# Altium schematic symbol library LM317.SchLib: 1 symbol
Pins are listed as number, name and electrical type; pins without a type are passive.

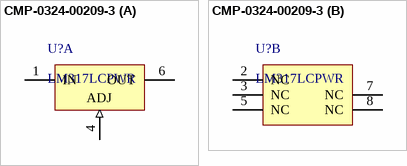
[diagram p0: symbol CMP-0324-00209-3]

## CMP-0324-00209-3
designator U?, comment LM317LCPWR
Adjustable Regulator with 3.7 to 38 V Input and 1.2 to 32 V Output, 0 to 125 degC, 8-Pin TSSOP (PW), Green (RoHS & no Sb/Br); Manufacturer: Texas Instruments; Iout(Max)(A): 0.1; Vin(Min)(V): 3.7; Vin(Max)(V): 38; Vout(Min)(V): 1.2; Vout(Max)(V): 32
footprint PW0008A_M (SOP, 8-Leads, Body 4.5x3.1mm, Pitch 0.65mm, IPC Low Density)
footprint PW0008A_N (SOP, 8-Leads, Body 4.5x3.1mm, Pitch 0.65mm, IPC Medium Density)
footprint PW0008A_L (SOP, 8-Leads, Body 4.5x3.1mm, Pitch 0.65mm, IPC High Density)
part A pins: 1 IN (power), 4 ADJ (in), 6 OUT (power)
part B pins: 2 NC, 3 NC, 5 NC, 7 NC, 8 NC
